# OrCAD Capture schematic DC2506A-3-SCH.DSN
size Custom
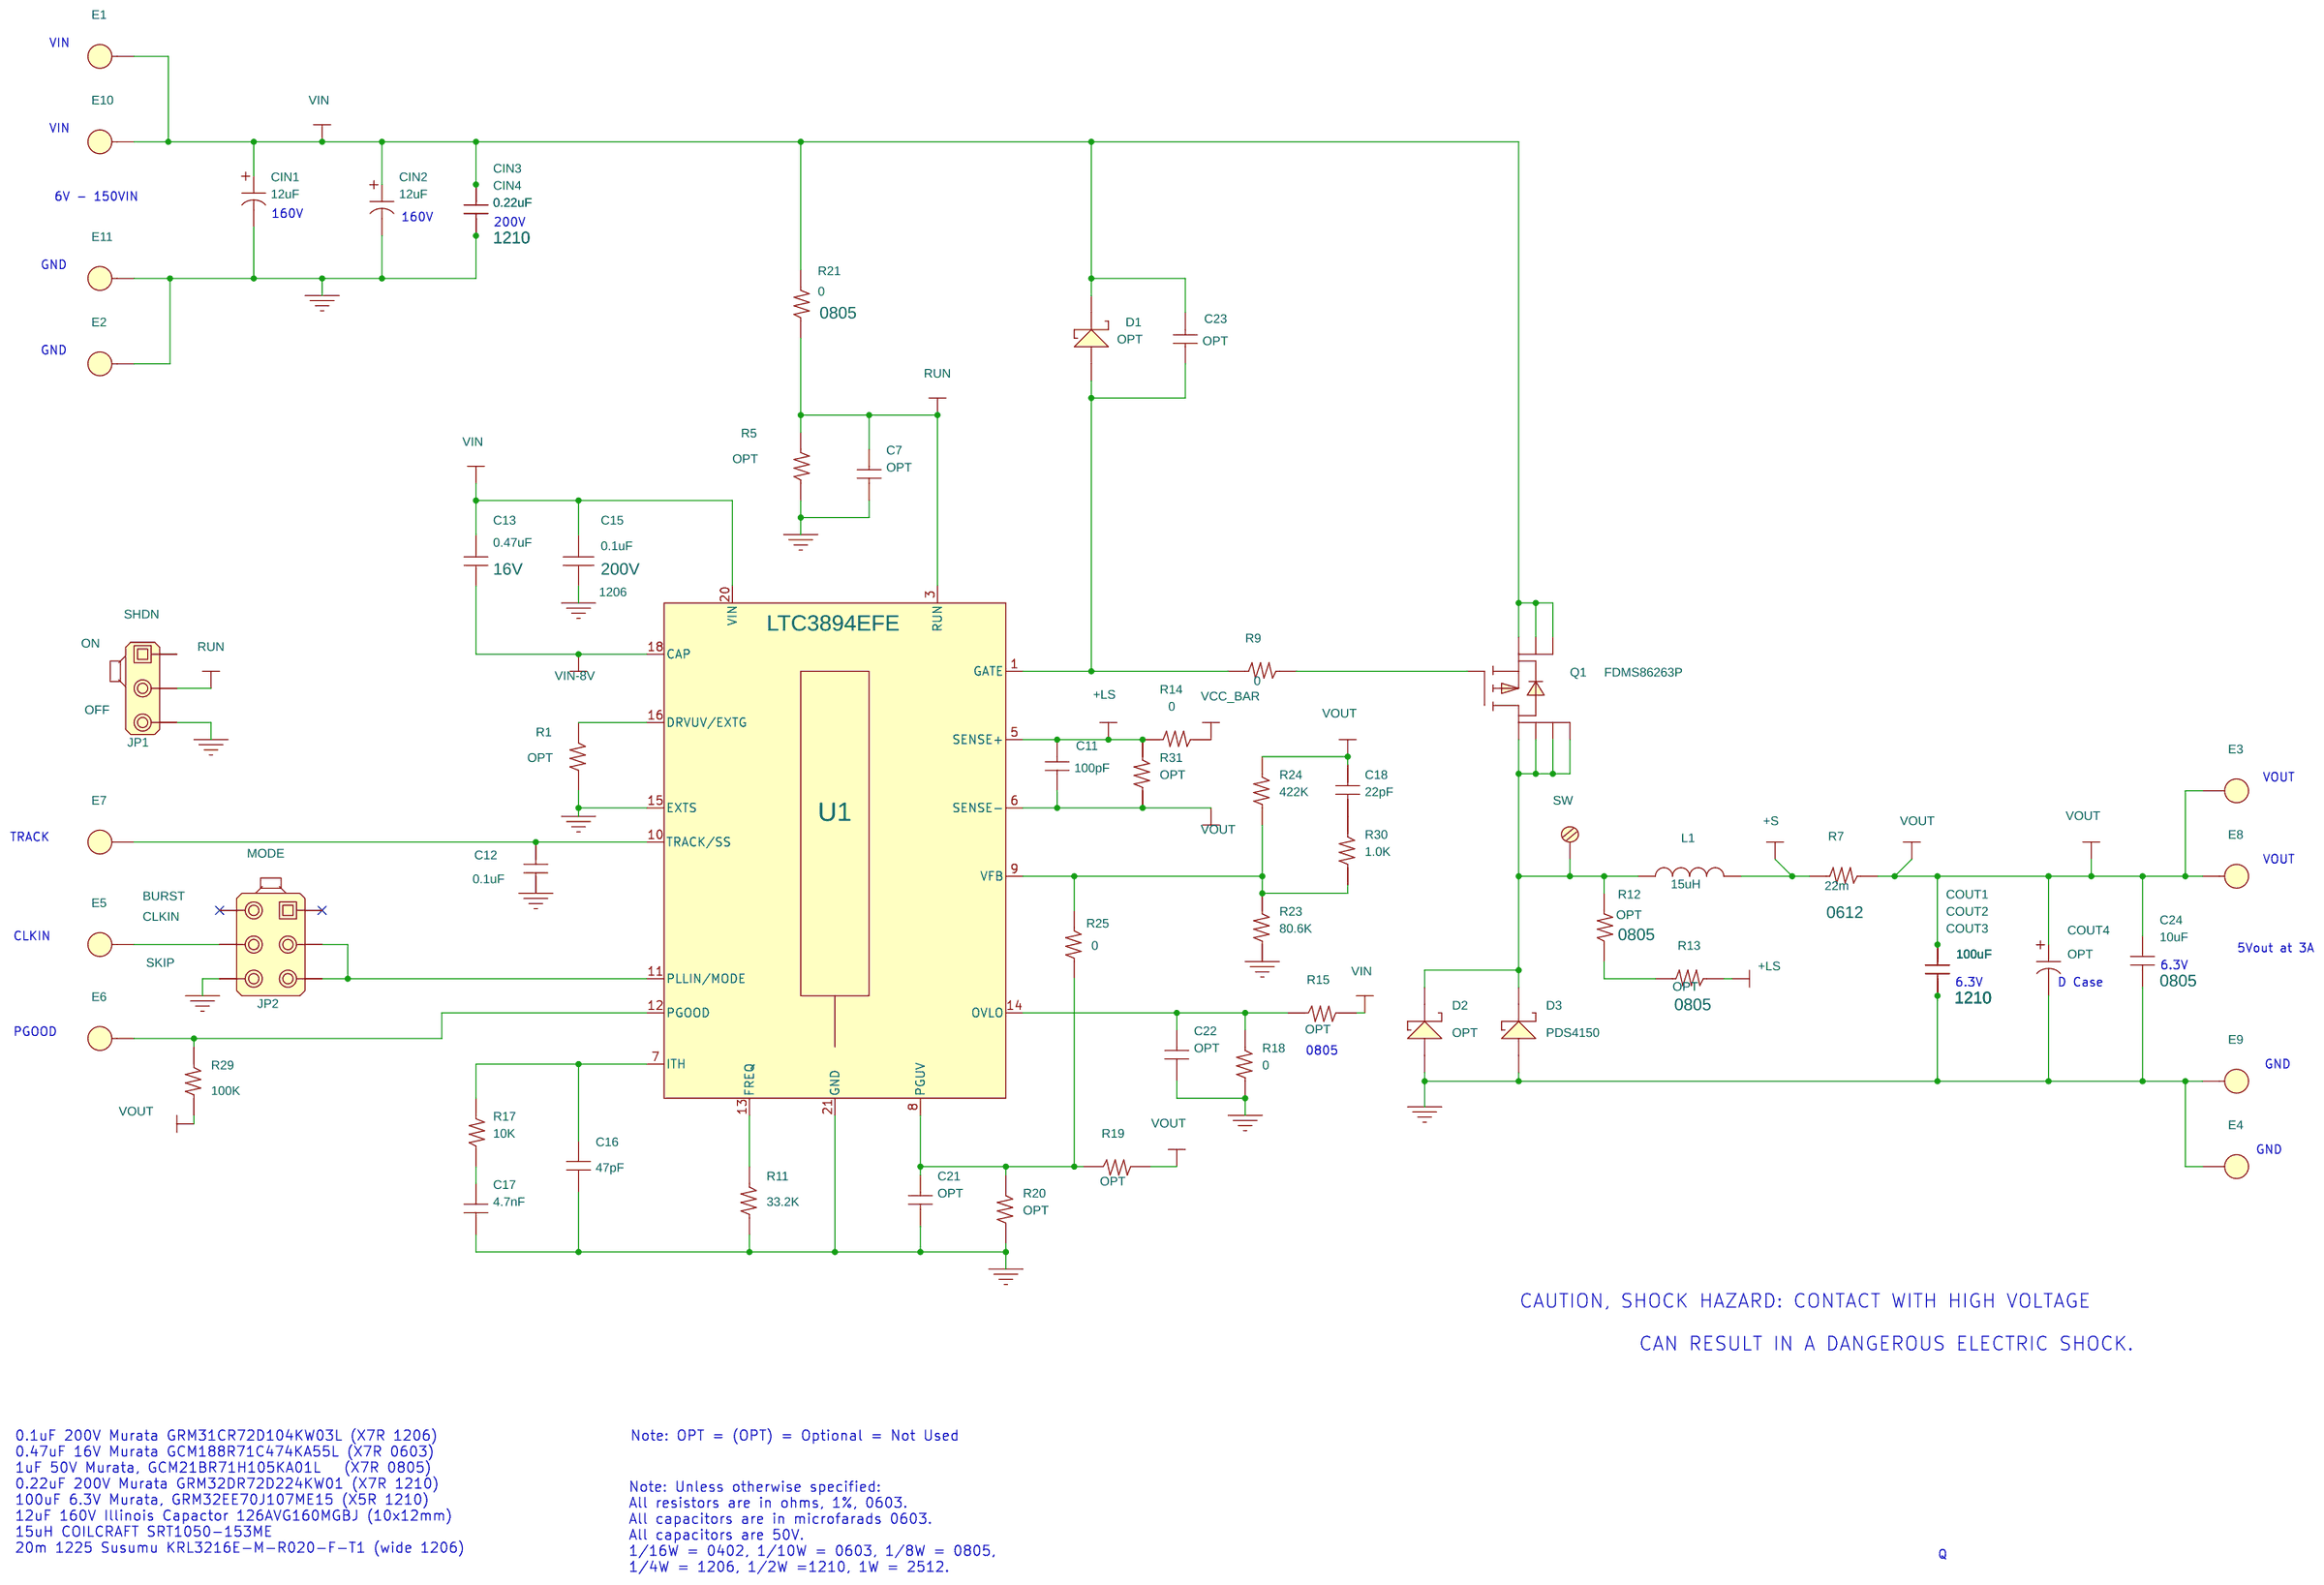
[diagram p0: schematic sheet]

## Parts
C7  OPT  [0603]
C11  100pF  [0603]
C12  0.1uF  [0603]
C13  0.47uF  [0603]
C15  0.1uF  [1206]
C16  47pF  [0603]
C17  4.7nF  [0603]
C18  22pF  [0603]
C21  OPT  [0603]
C22  OPT  [0603]
C23  OPT  [0603]
C24  10uF  [0805]
CIN1  12uF  [CAP-TH-10D]
CIN2  12uF  [CAP-TH-10D]
CIN3  0.22uF  [1210]
CIN4  0.22uF  [1210]
COUT1  100uF  [1210]
COUT2  100uF  [1210]
COUT3  100uF  [1210]
COUT4  OPT  [7343]
D1  OPT  [SOD123]
D2  OPT  [POWERDI5-2PIN]
D3  PDS4150  [POWERDI5-2PIN]
E1  E_0  [TP\MMX\2501-2]
E2  E_0  [TP\MMX\2501-2]
E3  E_0  [TP\MMX\2501-2]
E4  E_0  [TP\MMX\2501-2]
E5  E_0  [TP\MMX\2501-2]
E6  E_0  [TP\MMX\2501-2]
E7  E_0  [TP\MMX\2501-2]
E8  E_0  [TP\MMX\2501-2]
E9  E_0  [TP\MMX\2501-2]
E10  E_0  [TP\MMX\2501-2]
E11  E_0  [TP\MMX\2501-2]
JP1  Sgl. Row 3 Pins 2mm Ctrs.  [HD1X3-079]
JP2  Dbl. Row 2 x 3 2mm Ctrs.  [HD2X3-079]
L1  15uH  [IND-SRT1050]
Q1  FDMS86263P  [SO8-POWERPAK]
R1  OPT  [0603]
R5  OPT  [0603]
R7  22m  [0612]
R9  0  [0603]
R11  33.2K  [0603]
R12  OPT  [0805]
R13  OPT  [0805]
R14  0  [0603]
R15  OPT  [0805]
R17  10K  [0603]
R18  0  [0603]
R19  OPT  [0603]
R20  OPT  [0603]
R21  0  [0805]
R23  80.6K  [0603]
R24  422K  [0603]
R25  0  [0603]
R29  100K  [0603]
R30  1.0K  [0603]
R31  OPT  [0603]
SW  TURRET\2501-2_2  [PAD065-040]
U1  LTC3894EFE  [TSSOP20EFE-16]
XJP1  SHUNT  [NONE]
XJP2  SHUNT  [NONE]

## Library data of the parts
C7 C11 C12 C16-C18 C21-C24 CIN3 CIN4 COUT1-COUT3 = CAP-NP
C13 = CAP-NP: 1ST PART FIELD: 16V
C15 = 12061C104KAT2A_0: 1ST PART FIELD: 200V; 2ND PART FIELD: 10%, 0206; 3RD PART FIELD: X7R; 4TH PART FIELD: AVX; 7TH PART FIELD: CAP.
CIN1 CIN2 COUT4 = CAP
D1 = DIODE_SCHOTTKY_1_v2: DIODE, OPTION; Part Number: OPTION
D2 D3 = DIODE_SCHOTTKY_1
E1-E11 = E_0: TURRET; Part Number: MILL MAX 2501-2-00-80-00-00-07-0
JP1 = Samtec_TMM-103-02-L-S: HEADER, 3PIN SINGLE ROW 2mm; 11th Part Field: OFF; 12th Part Field: SHDN; 9th Part Field: ON; Part Number: SAMTEC TMM-103-02-L-S
JP2 = Samtec_TMM-103-02-L-D: HEADER, 3PIN DOUBLE ROW 2mm; 10th Part Field: CLKIN; 11th Part Field: SKIP; 12th Part Field: MODE; 9th Part Field: BURST; Part Number: SAMTEC TMM-103-02-L-D
L1 = INDUCTOR
Q1 = SI7456DP_0: 1ST PART FIELD: 150V; 2ND PART FIELD: POWERPAK SO-8; 3RD PART FIELD: N-CHANNEL; 5TH PART FIELD: Si7450DP; 7TH PART FIELD: FET; opt: *
R1 R7 R9 R11 R25 R29 R31 = R: V: 1%
R5 R12-R15 R17-R21 R23 R24 R30 = R
SW = TURRET_2501-2_2
U1 = LT1339_24: 3RD PART FIELD: ANALOG; 4TH PART FIELD: LINEAR TECH.; 5TH PART FIELD: LTC7000EMS16E; 7TH PART FIELD: I.C.
XJP1 XJP2 = Samtec_2SN-BK-G: SHUNT, 2mm; Part Number: SAMTEC 2SN-BK-G

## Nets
GND: C7.2 C12.1 C15.2 C16.2 C17.2 C21.2 C22.2 C24.2 CIN1.2 CIN2.2 CIN3.2 CIN4.2 COUT1.2 COUT2.2 COUT3.2 COUT4.2 D2.1 D3.1 E2.1(A) E4.1(A) E9.1(A) E11.1(A) JP1.3 JP2.6 R1.2 R5.1 R11.2 R18.2 R20.2 R23.2 U1.15(EXTS) U1.21(GND)
VIN: C13.2 C15.1 C23.2 CIN1.1 CIN2.1 CIN3.1 CIN4.1 D1.1 E1.1(A) E10.1(A) Q1.1 Q1.2 Q1.3 R15.2 R21.2 U1.20(VIN)
VIN-8V: C13.1 U1.18(CAP)
+LS: C11.2 R13.1 R14.2 R31.1 U1.5(SENSE+)
+S: L1.2 R7.2 R14.1
-S: C11.1 C18.1 C24.1 COUT1.1 COUT2.1 COUT3.1 COUT4.1 E3.1(A) E8.1(A) R7.1 R19.2 R24.1 R29.2 R31.2 U1.6(SENSE-)
RUN: C7.1 JP1.2 R5.2 R21.1 U1.3(RUN)
N17566562: C22.1 R15.1 R18.1 U1.14(OVLO)
N17566576: C21.1 R19.1 R20.1 R25.2 U1.8(PGUV)
N17566644: C17.1 R17.1
N17566693: R23.1 R24.2 R25.1 R30.2 U1.9(VFB)
N17566896: R1.1 U1.16(DRVUV/EXTG)
N17567101: C23.1 D1.2 R9.2 U1.1(GATE)
N17567135: C16.1 R17.2 U1.7(ITH)
N17567475: Q1.4 R9.1
N17567904: C12.2 E7.1(A) U1.10(TRACK/SS)
N17567987: E6.1(A) R29.1 U1.12(PGOOD)
N17597627: R11.1 U1.13(FREQ)
N17618158: D2.2 D3.2 L1.1 Q1.5 Q1.6 Q1.7 Q1.8 R12.2 SW.1
N17618162: R12.1 R13.2
N17638627: JP2.3 JP2.5 U1.11(PLLIN/MODE)
N17638636: E5.1(A) JP2.4
N17660644: C18.2 R30.1

Not connected (* = marked no-connect by the designer): JP1 1; JP2 1* 2*

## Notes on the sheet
- VIN
- VIN
- 6V - 150VIN
- 160V
- 160V
- 200V
- GND
- GND
- VOUT
- TRACK
- VOUT
- CLKIN
- 5Vout at 3A
- 6.3V
- 6.3V
- D Case
- PGOOD
- 0805
- GND
- GND
- CAUTION, SHOCK HAZARD: CONTACT WITH HIGH VOLTAGE
- CAN RESULT IN A DANGEROUS ELECTRIC SHOCK.
- 0.1uF 200V Murata GRM31CR72D104KW03L (X7R 1206)
  0.47uF 16V Murata GCM188R71C474KA55L (X7R 0603)
  1uF 50V Murata, GCM21BR71H105KA01L   (X7R 0805)
  0.22uF 200V Murata GRM32DR72D224KW01 (X7R 1210)
  100uF 6.3V Murata, GRM32EE70J107ME15 (X5R 1210)
  12uF 160V Illinois Capactor 126AVG160MGBJ (10x12mm)
  15uH COILCRAFT SRT1050-153ME
  20m 1225 Susumu KRL3216E-M-R020-F-T1 (wide 1206)
- Note: OPT = (OPT) = Optional = Not Used
- Note: Unless otherwise specified:
  All resistors are in ohms, 1%, 0603.
  All capacitors are in microfarads 0603.
  All capacitors are 50V.
  1/16W = 0402, 1/10W = 0603, 1/8W = 0805,
  1/4W = 1206, 1/2W =1210, 1W = 2512.
- Q
